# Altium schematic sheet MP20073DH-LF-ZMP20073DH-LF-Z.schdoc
size 127 x 101 mm
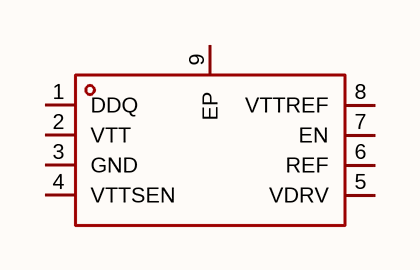
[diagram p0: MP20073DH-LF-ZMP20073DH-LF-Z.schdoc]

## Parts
U?  mp20073dh-lf-z  [MSOP-8_L3.0-W3.0-P0.65-LS4.9-BL-EP-3]  (value not drawn)

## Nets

Not connected (* = marked no-connect by the designer): U? 1(DDQ) 2(VTT) 3(GND) 4(VTTSEN) 5(VDRV) 6(REF) 7(EN) 8(VTTREF) 9(EP)

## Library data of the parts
U? = mp20073dh-lf-z: 输出极性:正极;工作电压:6V;输出电压:3.3V;输出电流:2A;电源纹波抑制比(PSRR):-;输出类型:固定;; Manufacturer: MPS(芯源); AddInBom: yes; ModelId: 66911edc018749b0878ca7e763914899; ModelTransform: 118.11,192.913,0,0,0,0,0,0,0; Output Configuration: 正极; Voltage - Supply: 6V; Output Voltage: 3.3V; Output Current: 2A; Output Type: 固定; Number of Outputs: 1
